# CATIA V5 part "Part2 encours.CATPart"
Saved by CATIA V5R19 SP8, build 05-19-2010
Part number: Part2 encours.1
Bounding box of the stored display mesh (mm): x 0 to 100, y 0 to 600, z 0 to 155
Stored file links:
  G:\EU_thinkMotion\CFAO_2010\SIL_groupe2\SIL_groupe2\A reprendre\fnongaibaa\fnongaibaa\Part2 encours.CATPart
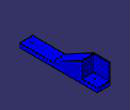
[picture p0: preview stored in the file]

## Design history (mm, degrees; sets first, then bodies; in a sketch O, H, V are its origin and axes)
Parameters
  `Longueur.1 A` = 0 mm
Body1 (main body)
  Sketch1 on yz-plane, origin (0, 0, 0), H (0, 1, 0), V (0, 0, 1)
    line L1 (0, 0) -> (0, 34)
    line L2 (0, 34) -> (250, 34)
    line L3 (250, 34) -> (475, 155)
    line L4 (0, 0) -> (600, 0)
    line L5 (600, 0) -> (600, 155)
    line L6 (600, 155) -> (475, 155)
    length L4 = 600
    length L1 = 34
    length L2 = 250
    length L6 = 125
    length L5 = 155
    vertical: L1 V, L5 V
    horizontal: L2 H, L4 H, L6 H
  Pad1: profile Sketch1, direction (1, 0, 0), length 100
  Sketch2 on face of Pad1 from Sketch1.L2, origin (16.1115, 28.9606, 34), H (1, 0, 0), V (0, 1, 0)
    point P1 (33.8885, 13.0394)
    axis line L1 (33.8885, 30) -> (33.8885, -60)
    reference projected line E1 (-16.1115, 53.571) -> (-16.1115, -28.9606) from edge [start face of Pad1 | face of Pad1 from Sketch1.L2]
    reference projected line E2 (83.8885, 53.571) -> (83.8885, -28.9606) from edge [face of Pad1 from Sketch1.L2 | end face of Pad1]
    reference projected line E3 (-16.1115, -28.9606) -> (3.8885, -28.9606) from edge [face of Pad1 from Sketch1.L1 | face of Pad1 from Sketch1.L2]
    distance P1 E3 = 42
    vertical: L1 V
    symmetry: E1 E2 L1
    coincidence: P1 L1
  Hole1: placed by Sketch2, at (50, 42, 34) direction (0, 0, -1), diameter 10, through (limit type 6)
  Sketch3 on end face of Pad1, origin (100, 0, 0), H (0, 1, 0), V (0, 0, 1)
    line L1 (480, 34) -> (600, 34)
    line L2 (600, 34) -> (600, 155)
    line L3 (600, 155) -> (480, 155)
    line L4 (480, 155) -> (480, 34)
    reference projected line E1 (600, 0) -> (600, 155) from edge [face of Pad1 from Sketch1.L5 | end face of Pad1]
    reference projected line E2 (600, 155) -> (475, 155) from edge [face of Pad1 from Sketch1.L6 | end face of Pad1]
    reference projected line E3 (250, 34) -> (0, 34) from edge [face of Pad1 from Sketch1.L2 | end face of Pad1]
    length L3 = 120
    horizontal: L1 H, L3 H
    vertical: L2 V, L4 V
    coincidence: L2 E1, E2 L3, L1 E3
  Pocket1: profile Sketch3, direction (-1, 0, 0), length 90
  Sketch4 on face of Pocket1 from Sketch3.L1, origin (28.4009, 522.4264, 34), H (1, 0, 0), V (0, 1, 0)
    point P1 (21.5991, 4.5736)
    axis line L1 (21.5991, -200.4581) -> (21.5991, 80.2553)
    reference projected line E1 (-28.4009, 77.5736) -> (-28.4009, -47.4264) from edge [start face of Pad1 | face of Pad1 from Sketch1.L6]
    reference projected line E2 (71.5991, -42.4264) -> (71.5991, 77.5736) from edge [end face of Pad1 | face of Pocket1 from Sketch3.L1]
    reference projected line E3 (71.5991, 77.5736) -> (-18.4009, 77.5736) from edge [face of Pad1 from Sketch1.L5 | face of Pocket1 from Sketch3.L1]
    distance P1 E3 = 73
    symmetry: E1 E2 L1
    coincidence: P1 L1
  Hole2: placed by Sketch4, at (50, 527, 34) direction (0, 0, -1), diameter 10, through (limit type 6)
